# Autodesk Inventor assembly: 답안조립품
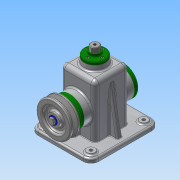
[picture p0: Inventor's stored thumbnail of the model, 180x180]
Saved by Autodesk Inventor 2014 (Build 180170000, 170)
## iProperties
Created: 2015-12
Part Number: 답안조립품
Document SubType Name: Assembly
Designer: Administrator
Author: Administrator
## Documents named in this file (19)
- D:\451225V1005\답안조립품.iam
- D:\451225V1005\1-본체.ipt
- D:\451225V1005\V-벨트풀리.ipt
- D:\451225V1005\뒤커버.ipt
- D:\451225V1005\멈춤링 15 x 1.ipt
- D:\451225V1005\베어링 15 x 35 x 11.ipt
- D:\451225V1005\볼트 M4 x 10.ipt
- D:\451225V1005\볼트 M6 x 12.ipt
- D:\451225V1005\앞커버.ipt
- D:\451225V1005\오일실 15 25 7.ipt
- D:\451225V1005\와셔.ipt
- D:\451225V1005\키 5 x 5 x 14.ipt
- D:\451225V1005\편심축.ipt
- D:\451225V1005\슬라이드바.ipt
- D:\451225V1005\링크.ipt
- D:\451225V1005\고정핀.ipt
- D:\451225V1005\상부부시.ipt
- D:\451225V1005\볼트 M3 x 8.ipt
- D:\451225V1005\멈춤링 6 x 5.ipt
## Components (16 placed, 6 different names)
1. 1-본체:1
2. ISO 4762 M4 x 10:1
3. ISO 4762 M4 x 10:2
4. ISO 4762 M4 x 10:3
5. ISO 4762 M4 x 10:4
6. ISO 4762 M4 x 10:5
7. ISO 4762 M4 x 10:6
8. ISO 4762 M4 x 10:7
9. ISO 4762 M4 x 10:8
10. V-벨트풀리:1 — 각도:2
11. ISO 4018 M6 x 12:1
12. 고정핀:1
13. ISO 4762 M3 x 8:1
14. ISO 4762 M3 x 8:2
15. ISO 4762 M3 x 8:3
16. ISO 4762 M3 x 8:4
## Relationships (1: Angle 1)
- 각도:2 [Angle]: V-벨트풀리:1
